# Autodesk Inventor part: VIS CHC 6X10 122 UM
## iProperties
Shininess: 20.0
Angle Display Precision: 2
Document Length Units: 11269
Document Angle Units: 11279
Document Time Units: 11290
Document Mass Units: 11283
Document Length Units Precision: 3
Document Angle Units Precision: 2
Created: 2002-02
Part Number: VIS CHC 6X10 122 UM
Material: Par défaut
Catalog Web Link: www.traceparts.com
Description: Vis tête cylindrique a 6 pans creux
Vendor: RABOURDIN
Document SubType Name: Modélisation
Standard: 527 - 6 x 10
Designer: Administrateur
Density: 0.0
Volumn: 0.0
Area: 0.0
PropertySet Name: Model Information
Control State: 0
Master: False
Checked Out: False
Author: Administrateur
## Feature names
1. Base1
